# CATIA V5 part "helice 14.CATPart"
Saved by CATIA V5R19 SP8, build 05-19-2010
Part number: helice 14
Bounding box of the stored display mesh (mm): x -17.321 to 17.321, y -30 to 195, z -10 to 20
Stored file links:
  G:\EU_thinkMotion\CFAO_2010\MMS_groupe2\MMS_groupe2\A reprendre\splanchenault\Planchenault\helice 14.CATPart
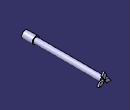
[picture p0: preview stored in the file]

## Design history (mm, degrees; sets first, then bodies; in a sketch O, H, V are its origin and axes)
Body1 (main body)
  Sketch1 on yz-plane, origin (0, 0, 0), H (0, 1, 0), V (0, 0, 1)
    line L1 (0, 0) -> (-30, 0)
    line L2 (-30, 0) -> (-30, -10)
    line L3 (0, -10) -> (-30, -10)
    line L4 (0, -10) -> (0, -7.5)
    line L5 (0, -7.5) -> (190, -7.5)
    line L6 (190, -7.5) -> (190, 0)
    line L7 (190, 0) -> (0, 0)
    length L6 = 7.5
    length L2 = 10
    horizontal: L1 H, L3 H, L5 H, L7 H
    vertical: L2 V, L4 V, L6 V
  Shaft1: profile Sketch1, axis Sketch1.L1, angle 360
  Sketch2 on face of Shaft1 from Sketch1.L6, origin (0, 190, 0), H (-1, 0, 0), V (0, 0, 1)
    construction line L1 (19.3649, -11.1803) -> (-19.3649, 11.1803)
    axis line L2 (-19.3649, -11.1803) -> (19.3649, 11.1803)
    line L3 (0, 0) -> (5.7735, 10)
    point P5 (5.7735, 10)
    line L4 (5.7735, 10) -> (0, 20)
    point P6 (0, 20)
    line L5 (0, 20) -> (-5.7735, 10)
    point P7 (-5.7735, 10)
    line L6 (-5.7735, 10) -> (0, 0)
    point P8 (-11.547, 0)
    point P9 (-17.3205, -10)
    line L7 (-17.3205, -10) -> (-11.547, 0)
    point P10 (-5.7735, -10)
    line L8 (-5.7735, -10) -> (-17.3205, -10)
    point P11 (0, 0)
    line L9 (0, 0) -> (-5.7735, -10)
    line L10 (-11.547, 0) -> (0, 0)
    point P12 (5.7735, -10)
    point P13 (17.3205, -10)
    line L11 (17.3205, -10) -> (5.7735, -10)
    point P14 (11.547, 0)
    line L12 (11.547, 0) -> (17.3205, -10)
    point P15 (0, 0)
    line L13 (0, 0) -> (11.547, 0)
    line L14 (5.7735, -10) -> (0, 0)
    angle L1 V = 60
    angle L2 V = 60
    coincidence: L1 O, P6 V, O P11, O P15, P11 P15
    perpendicularity: L3 L1, L4 L2
    parallelism: L5 L3, L6 L4
    symmetry: P7 P8 L1, P6 P9 L1, L5 L7 L1, P5 P10 L1, L4 L8 L1, O P11 L1, L3 L9 L1, L6 L10 L1, P7 P12 L2, P6 P13 L2, L5 L11 L2, P5 P14 L2, L4 L12 L2, O P15 L2, L3 L13 L2, L6 L14 L2
  Pad1: profile Sketch2, direction (0, 1, 0), length 5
